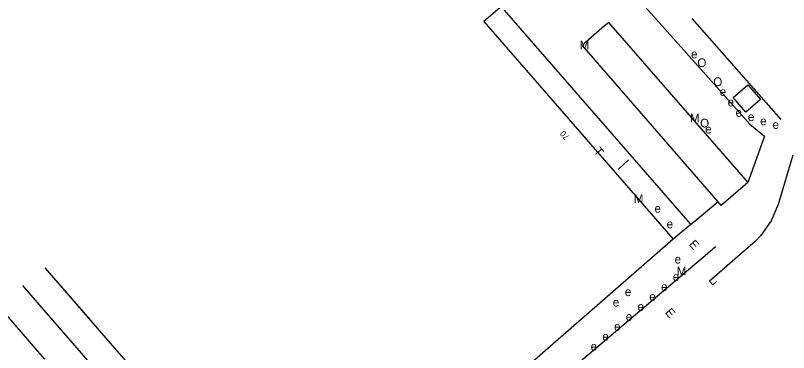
# Model space of a CAD drawing. Extents: x 81617 to 82144, y 454649 to 455150.
# Drawn here: x 81697.5 to 81786.6, y 454815.9 to 454854.8 of the extents above; entities that cross this region are included whole.
import ezdxf

# ---------------------------------------------------------------- set-up
doc = ezdxf.new("R2010")
doc.units = 0
doc.layers.add('B-WE-OG-TOPOGRAFIE-G', color=7, linetype='Continuous')

msp = doc.modelspace()

# ---------------------------------------------------------------- linework, layer by layer
at = {"layer": 'B-WE-OG-TOPOGRAFIE-G'}
for p, q in [((81775.327, 454830.766), (81753.876, 454855.395)), ((81765.889, 454853.971), (81781.941, 454835.537)), ((81775.486, 454854.437), (81785.758, 454842.81)), ((81778.547, 454833.294), (81762.859, 454851.327)), ((81768.184, 454838.156), (81767.001, 454837.033)), ((81781.941, 454835.537), (81778.893, 454832.897)), ((81778.893, 454832.897), (81778.547, 454833.294)), ((81773.327, 454828.992), (81771.79, 454827.664)), ((81782.809, 454828.741), (81777.544, 454824.149)), ((81723.239, 454800), (81700.883, 454825.688)), ((81706.063, 454819.736), (81700.883, 454825.688)), ((81700, 454821.713), (81698.298, 454823.666)), ((81777.911, 454823.73), (81777.544, 454824.149)), ((81777.911, 454823.73), (81778.348, 454824.117)), ((81718.925, 454800), (81700, 454821.713)), ((81700, 454816.095), (81700.811, 454815.163))]:
    msp.add_line(p, q, dxfattribs=at)
for points in [[(81747.885, 454862.474), (81753.612, 454855.894), (81751.488, 454854.074), (81773.327, 454828.992)], [(81769.591, 454861.283), (81767.56, 454858.65), (81782.174, 454842.275), (81783.862, 454840.879), (81781.941, 454835.537)], [(81762.859, 454851.327), (81763.263, 454851.751), (81765.404, 454853.643), (81765.889, 454853.971)], [(81781.966, 454846.806), (81783.422, 454845.091), (81781.707, 454843.635), (81780.252, 454845.349), (81781.966, 454846.806)], [(81787.136, 454838.686), (81785.453, 454833.006), (81784.632, 454831.127), (81783.463, 454829.444), (81782.809, 454828.741)], [(81778.547, 454833.294), (81775.862, 454831.087), (81775.375, 454830.685)], [(81775.375, 454830.685), (81773.327, 454828.992)], [(81775.823, 454826.113), (81777.012, 454827.109), (81778.222, 454828.15)], [(81771.79, 454827.664), (81747.424, 454806.414), (81747.047, 454806.839), (81741.817, 454810.382), (81736.3, 454802.291), (81736.227, 454802.185), (81734.827, 454800.472), (81734.31, 454800)], [(81745.006, 454800), (81748.474, 454802.942), (81749.425, 454803.721), (81775.343, 454825.711), (81775.823, 454826.113)], [(81695.39, 454821.39), (81700, 454816.095)]]:
    msp.add_lwpolyline(points, dxfattribs=at)

# ---------------------------------------------------------------- texts
for s, p in [('M', (81762.56, 454850.89)), ('e', (81775.399, 454849.847)), ('O', (81776.129, 454848.846)), ('O', (81777.972, 454846.648)), ('e', (81778.708, 454845.503)), ('e', (81779.622, 454844.307)), ('M', (81775.278, 454842.472)), ('e', (81780.536, 454843.11)), ('e', (81781.955, 454842.615)), ('O', (81776.448, 454841.878)), ('e', (81783.379, 454842.124)), ('e', (81784.798, 454841.715)), ('e', (81777.031, 454841.192)), ('M', (81768.794, 454833.185)), ('e', (81771.189, 454832.056)), ('e', (81772.58, 454830.262)), ('e', (81773.502, 454826.198)), ('M', (81773.753, 454824.821)), ('e', (81773.288, 454824.188)), ('e', (81771.934, 454823.04)), ('e', (81767.763, 454822.446)), ('e', (81770.58, 454821.893)), ('e', (81766.373, 454821.241)), ('e', (81769.227, 454820.746)), ('e', (81767.873, 454819.599)), ('e', (81766.519, 454818.452)), ('e', (81765.166, 454817.305)), ('e', (81763.812, 454816.157))]:
    msp.add_text(s, height=1, dxfattribs=at).set_placement(p)
for s, height, rotation, p in [('70', 0.7, 131.09679, (81761.421, 454840.802)), ('T', 1, 309.80561, (81764.117, 454839.1)), ('E', 1, 311.37815, (81775.098, 454828.378)), ('E', 1, 310.75007, (81772.344, 454820.528))]:
    msp.add_text(s, height=height, rotation=rotation, dxfattribs=at).set_placement(p)

doc.saveas('drawing.dxf')
